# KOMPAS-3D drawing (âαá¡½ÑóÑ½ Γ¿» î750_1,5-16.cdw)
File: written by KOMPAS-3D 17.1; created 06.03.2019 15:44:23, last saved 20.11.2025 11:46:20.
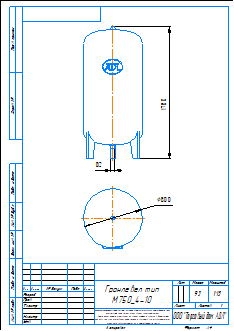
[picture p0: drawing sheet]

Sheet 1: A4, portrait

Title block, sheet 1: name: Гранлевел тип / М750_4-10; mass: 93; sheets: 1; sheet format: A4; stored path: C:\Users\kka\KOMPAS_Work\!Trash\ГРАНЛЕВЕЛ тип А Расширительный бак\KOMPAS 2D\Гранлевел тип А100_1,5-16.cdw

Views: Спереди 1, Спереди, Проекционный вид 2
Referenced files in C:\Users\mipv\Desktop\Тип А\SAT\: Гранлевел тип А750_4-10.a3d
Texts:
  kka
  adl
  Гранлевел тип А750_4-10
  Рама для чертежей
  Лит-Масса-Масштаб
  Материал-Предприятие
  Масштаб
  Изм.
  Лист
  № докум.
  Подп.
  Дата
  Лит.
  Разраб.
  Пров.
  Т.контр.
  Листов
  Внимание! Данный продукт является объектом авторского права ООО «Торговый Дом АДЛ».
  Запрещается изменение, копирование, распространение
  (в том числе путем копирования на другие сайты и ресурсы в Интернете)
  или любое иное использование информации и объектов без предварительного
  согласия правообладателя (ООО «Торговый Дом АДЛ»).
  Н.контр.
  Утв.
  ООО "Торговый дом АДЛ"
  Изменение
  Номер документа
  Подпись
  Обозначение документа
  Наименование изделия
  Масса изделия по ГОСТ 2.109-73
  Порядковый номер листа
  Общее количество листов в документе
  Характер работы, выполненной лицом, подписавшим документ
  Наименование или индекс предприятия, выпускающего документ
  Инв. № подл.
  Подп. и дата
  Взам. инв. №
  Инв. № дубл.
  Инвентарный номер подлинника по ГОСТ 2.501-68
  Подпись принявшего подлинник в отдел технической документации
  Инвентарный номер подлинника, взамен которого выпущен данный подлинник
  Инвентарный номер дубликата по ГОСТ 2.502-68
  Подпись принявшего дубликат в отдел технической документации
  Справ. №
  Перв. примен.
  Обозначение документа, взамен или на основании которого выпущен данный документ
  Обозначение документа, в котором впервые записан данный документ
  Подпись лица, копировавшего чертеж
  Обозначение формата листа
  !Рама для чертежа
Dimensions and other numbers on the sheet: 1780; 800; 1:15; 1; 93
